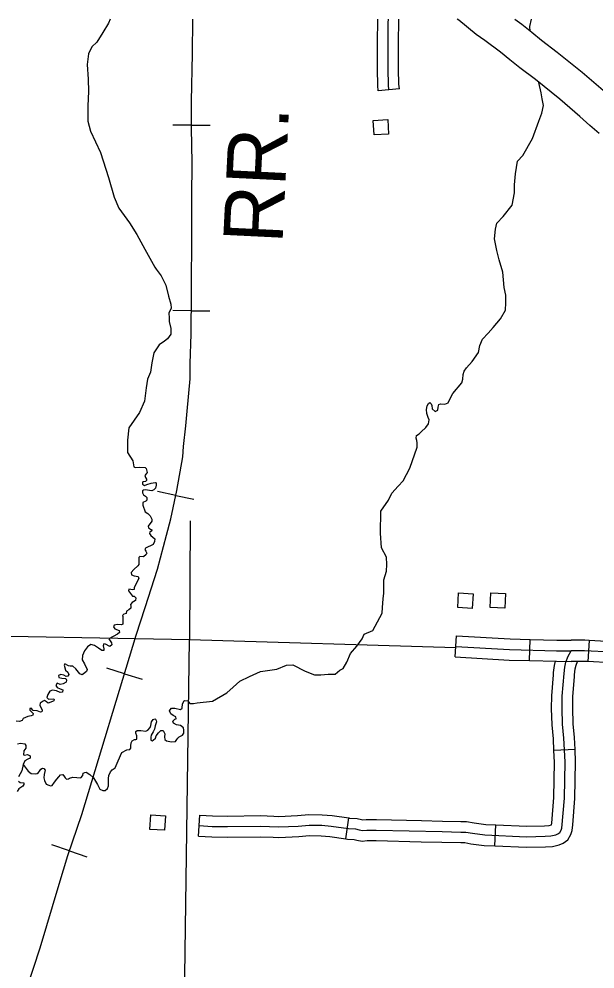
# Model space of a CAD drawing. Extents: x 61396 to 64680, y 55472 to 57605.
# Drawn here: x 62085.6 to 62213.6, y 56474.2 to 56685.3 of the extents above; entities that cross this region are included whole.
import ezdxf

# ---------------------------------------------------------------- set-up
doc = ezdxf.new("R2010")
doc.units = 0
for name, color, linetype in [('15', 7, 'Continuous'), ('32', 7, 'Continuous'), ('35', 7, 'Continuous'), ('40', 7, 'Continuous'), ('45', 7, 'Continuous'), ('5', 7, 'Continuous'), ('56', 7, 'Continuous')]:
    doc.layers.add(name, color=color, linetype=linetype)

msp = doc.modelspace()

# ---------------------------------------------------------------- linework, layer by layer
at = {"layer": '15'}
for points in [[(62214.53, 56659.81), (62212.49, 56661.57), (62210.28, 56663.63), (62205.78, 56667.45), (62200.39, 56671.79), (62196.91, 56674.45), (62194.73, 56676.21), (62192.61, 56677.89), (62189.12, 56680.49), (62187.24, 56681.8), (62183.33, 56685), (62183, 56685.27)], [(62195.78, 56685.27), (62197.37, 56684.09), (62199.61, 56682.31), (62201.74, 56680.59), (62205.21, 56677.93), (62210.76, 56673.47), (62215.48, 56669.46)]]:
    msp.add_lwpolyline(points, dxfattribs=at)
at = {"layer": '32'}
for p, q in [((62170.14, 56669.74), (62165.47, 56669.34)), ((62182.54, 56543.52), (62182.81, 56548.2)), ((62199.09, 56542.71), (62199.22, 56547.39)), ((62212.31, 56547.16), (62212.06, 56542.48))]:
    msp.add_line(p, q, dxfattribs=at)
for points in [[(62165.47, 56669.34), (62165.37, 56670.52), (62165.31, 56674.11), (62165.31, 56680.62), (62165.34, 56684.51), (62165.37, 56685.27)], [(62167.81, 56669.54), (62167.71, 56670.64), (62167.65, 56674.13), (62167.65, 56680.61), (62167.68, 56684.45), (62167.72, 56685.27)], [(62170.14, 56669.74), (62170.05, 56670.76), (62169.99, 56674.15), (62169.99, 56680.6), (62170.02, 56684.39), (62170.06, 56685.27)], [(62182.81, 56548.2), (62194.76, 56547.52), (62199.22, 56547.39)], [(62199.22, 56547.39), (62205.13, 56547.23), (62208.35, 56547.22)], [(62212.31, 56547.16), (62211.36, 56547.22), (62208.35, 56547.22)], [(62228.59, 56546.6), (62227.04, 56546.55), (62220.19, 56546.77), (62217.39, 56546.88), (62212.31, 56547.16)], [(62182.68, 56545.86), (62194.66, 56545.17), (62205.09, 56544.89), (62208.35, 56544.87)], [(62245.16, 56544.7), (62243.79, 56544.59), (62238.85, 56544.62), (62227.04, 56544.2), (62220.1, 56544.43), (62217.28, 56544.54), (62211.29, 56544.87), (62208.35, 56544.87)], [(62182.54, 56543.52), (62194.56, 56542.83), (62199.09, 56542.71)], [(62199.09, 56542.71), (62205.05, 56542.54), (62208.34, 56542.53)], [(62212.06, 56542.48), (62211.23, 56542.53), (62208.34, 56542.53)], [(62228.75, 56541.92), (62227.04, 56541.86), (62220.02, 56542.09), (62217.17, 56542.2), (62212.06, 56542.48)]]:
    msp.add_lwpolyline(points, dxfattribs=at)
at = {"layer": '35'}
for points in [[(62105.84, 56685.27), (62105.46, 56684.33), (62104.2, 56682.24), (62102.87, 56680.13), (62101.79, 56679.08), (62101.05, 56677.56), (62100.73, 56675.17), (62100.95, 56671.91), (62101.04, 56669.15), (62100.88, 56665.98), (62100.91, 56662.59), (62101.53, 56660.31), (62103.73, 56655.59), (62105.5, 56650.05), (62106.73, 56645.67), (62107.76, 56643.27), (62110.14, 56639.94), (62111.79, 56637.38), (62113.57, 56634.1), (62115.83, 56630.11), (62116.09, 56629.7), (62117.17, 56628.21), (62118.22, 56626.09), (62118.81, 56623.68), (62119.32, 56621.92), (62119.43, 56621.02), (62118.93, 56619.88), (62119.01, 56618.88), (62119.01, 56618.06), (62119.37, 56616.46), (62119.35, 56615.24), (62118.64, 56614.23), (62117.96, 56613.69), (62116.72, 56612.89), (62115.54, 56611.09), (62115.09, 56608.89), (62114.83, 56606.81), (62114.19, 56605.2), (62113.83, 56603.29), (62113.52, 56600.33), (62112.38, 56597.84), (62109.98, 56594.42), (62109.7, 56591.7), (62109.74, 56588.94), (62110.87, 56587.11), (62111.12, 56585.73), (62111.44, 56585.57), (62112.33, 56585.69), (62113.63, 56585.63)], [(62199.24, 56682.57), (62199.15, 56683.63), (62199.51, 56685.27)], [(62190.96, 56616.72), (62192.6, 56618.62), (62193.71, 56620.58), (62193.84, 56622.22), (62193.84, 56623.92), (62193.45, 56625.63), (62193.12, 56629.03), (62192.34, 56631.78), (62191.81, 56633.81), (62191.29, 56636.43), (62191.55, 56638.59), (62191.81, 56639.9), (62193.25, 56641.4), (62195.22, 56643.89), (62195.74, 56646.64), (62195.74, 56648.41), (62195.94, 56650.83), (62196.4, 56653.71), (62197.57, 56654.95), (62199.74, 56658.75), (62201.18, 56662.55), (62201.83, 56664.38), (62202.16, 56666.02), (62201.9, 56667.52), (62201.63, 56668.9), (62201.15, 56671.13)], [(62122.19, 56527.72), (62121.48, 56528.25), (62120.6, 56528.43), (62119.95, 56528.78), (62119.83, 56529.25), (62120.25, 56529.66), (62120.54, 56529.78), (62120.48, 56530.19), (62119.89, 56530.49), (62119.36, 56530.9), (62119.07, 56531.54), (62119.19, 56531.78), (62119.48, 56532.13), (62120.25, 56532.13), (62121.48, 56531.84), (62121.89, 56532.13), (62121.95, 56533.07), (62122.3, 56533.72), (62122.48, 56533.84), (62123.13, 56533.72), (62123.6, 56533.19), (62124.36, 56533.19), (62125.19, 56533.31), (62128.6, 56533.66), (62131.77, 56535.54), (62133.18, 56536.83), (62134.71, 56538.13), (62136.83, 56539.19), (62139.3, 56540.24), (62142.94, 56540.83), (62145.06, 56541.66), (62146.47, 56541.77), (62149.18, 56540.36), (62151.3, 56539.54), (62152.71, 56539.54), (62154.35, 56539.66), (62155.88, 56539.66), (62156.94, 56540.6), (62157.65, 56540.95), (62158.47, 56542.36), (62159.29, 56544.24), (62160.7, 56545.89), (62161.88, 56547.54), (62162.35, 56548.59), (62164.23, 56549.42), (62166.34, 56553.22), (62166.41, 56554.53), (62166.54, 56556.43), (62166.67, 56557.67), (62166.73, 56559.05), (62166.67, 56560.68), (62167.32, 56562.58), (62167.39, 56564.02), (62167.26, 56565.66), (62166.21, 56567.75), (62165.95, 56571.03), (62166.01, 56575.87), (62167.72, 56578.36), (62168.5, 56579.93), (62169.88, 56581.44), (62170.99, 56582.61), (62172.5, 56585.49), (62174.07, 56590.14), (62174.07, 56591.12), (62174, 56591.58), (62173.87, 56592.11), (62173.94, 56592.7), (62174.53, 56593.09), (62174.98, 56593.55), (62176.03, 56594.53), (62176.62, 56595.31), (62176.75, 56596.17), (62176.56, 56596.69), (62176.23, 56597.61), (62176.16, 56598.46), (62176.29, 56599.31), (62176.62, 56599.83), (62176.95, 56600.03), (62177.21, 56599.77), (62177.34, 56599.37), (62177.47, 56598.65), (62178.13, 56598.06), (62178.72, 56598.33), (62178.78, 56599.05), (62178.91, 56599.57), (62179.31, 56599.77), (62180.22, 56599.7), (62181.01, 56599.96), (62181.34, 56600.81), (62182.06, 56602.06), (62184.02, 56604.41), (62184.22, 56605.2), (62184.35, 56606.25), (62184.54, 56607.03), (62185.07, 56607.75), (62186.31, 56609.13), (62187.75, 56611.16), (62188.01, 56612.73), (62188.6, 56614.1), (62189.85, 56615.48), (62190.96, 56616.72)], [(62113.63, 56585.63), (62113.9, 56585.42), (62114.07, 56584.5), (62113.86, 56584.21), (62113.57, 56583.82)], [(62113.57, 56583.82), (62113.71, 56583.4), (62113.96, 56583.05), (62113.96, 56582.71), (62113.73, 56582.52), (62113.16, 56582.4), (62113.03, 56582.23), (62113.07, 56581.91), (62113.5, 56581.64), (62114, 56581.81), (62114.99, 56582.14), (62115.84, 56582.31), (62116.09, 56582.19), (62116.09, 56581.68), (62115.94, 56580.98), (62115.58, 56580.65), (62115.1, 56580.44), (62114.63, 56580.52), (62113.75, 56580.67), (62113.24, 56580.6), (62113.05, 56580.39), (62113.03, 56580.01), (62113.24, 56579.55), (62113.71, 56579.25), (62114, 56578.92), (62114.04, 56578.37), (62113.79, 56578.09), (62113.14, 56577.82), (62113.14, 56577.27), (62113.66, 56575.75), (62114.25, 56575.35), (62114.76, 56574.85), (62115.12, 56574.09), (62115.1, 56573.69), (62114.3, 56572.59), (62114.36, 56572.17), (62114.82, 56571.93), (62115.14, 56571.79), (62115.16, 56571.66), (62114.95, 56571.43), (62114.68, 56571.26), (62114.59, 56570.96), (62114.91, 56570.46), (62115.82, 56569.78), (62115.75, 56569.15), (62115.39, 56568.47), (62113.75, 56567.69), (62113.54, 56567.36), (62113.79, 56567), (62114.04, 56566.58), (62113.9, 56566.26), (62113.31, 56565.75), (62112.44, 56565.84), (62112.25, 56565.61), (62112.25, 56564.02), (62112.04, 56563.75), (62111.13, 56562.91), (62110.56, 56562.27), (62110.62, 56561.75), (62111.23, 56561.53), (62112.07, 56561.37), (62112.23, 56560.95), (62111.78, 56560.14), (62111.2, 56558.86), (62111.17, 56558.47), (62110.91, 56558.44), (62110.01, 56558.54), (62109.95, 56558.21), (62110.17, 56557.89), (62110.85, 56557.02), (62111.17, 56557.02), (62111.59, 56556.67), (62111.52, 56556.06), (62110.75, 56555.58), (62110.36, 56555.19), (62110.49, 56554.81), (62110.46, 56554.32), (62110.04, 56554), (62109.53, 56553.68), (62109.4, 56553.2), (62108.89, 56553.01), (62108.6, 56552.75), (62108.69, 56552.49), (62108.69, 56550.79), (62108.4, 56550.66), (62107.47, 56550.72), (62106.73, 56550.59), (62106.57, 56550.18), (62106.92, 56549.73), (62107.89, 56549.37), (62107.92, 56548.95), (62107.5, 56548.6), (62105.57, 56547.54), (62106.18, 56546.63), (62106.24, 56546.17)], [(62106.24, 56546.17), (62105.79, 56545.81), (62104.82, 56546.34), (62104.44, 56546.39), (62104.29, 56546), (62104.49, 56545.33), (62104.49, 56544.94), (62104, 56544.94), (62103.28, 56545.47), (62102.36, 56546.05), (62101.59, 56546.24), (62100.82, 56545.76), (62100.14, 56544.84), (62099.71, 56543.83), (62099.61, 56542.86), (62100.19, 56541.95), (62100.77, 56540.74), (62100.62, 56540.31), (62099.95, 56539.78), (62099.61, 56539.53), (62099.13, 56539.78), (62098.21, 56540.84), (62097.58, 56541.47), (62097, 56541.47), (62096.57, 56541.56), (62095.8, 56542), (62095.65, 56541.71), (62095.94, 56540.6), (62096.42, 56540.11), (62096.67, 56539.58), (62096.47, 56539.24), (62096.09, 56539.15), (62095.56, 56539.49), (62094.88, 56539.58), (62094.35, 56539.39), (62094.45, 56538.95), (62095.12, 56538.76), (62096.04, 56538.71), (62096.13, 56538.38), (62096.09, 56537.94), (62095.41, 56537.51), (62094.78, 56537.36), (62094.11, 56537.65), (62093.82, 56537.17), (62094.06, 56536.69), (62094.78, 56536.44), (62095.31, 56536.2), (62095.27, 56535.67), (62094.73, 56535.62), (62093.96, 56535.96), (62093.05, 56536.11), (62092.42, 56535.91), (62091.98, 56535.14), (62091.79, 56534.47), (62092.13, 56534.13), (62093.33, 56534.22), (62093.43, 56534.08), (62093.33, 56533.79), (62093.05, 56533.6), (62092.08, 56533.26), (62091.74, 56533.5), (62091.26, 56533.84), (62090.97, 56533.65), (62090.29, 56533.21), (62090.24, 56532.78), (62090.73, 56531.67), (62090.68, 56531.28), (62090.39, 56531.23), (62089.67, 56531.52), (62088.75, 56531.62), (62088.31, 56532.15), (62088.02, 56532.05), (62087.98, 56531.67), (62088.36, 56531.28), (62088.75, 56530.94), (62088.7, 56530.6), (62088.31, 56530.41), (62087.59, 56530.27), (62086.53, 56529.83)], [(62086.53, 56529.83), (62086.32, 56529.42), (62085.72, 56529.17), (62084.94, 56529.21)], [(62086.52, 56519.58), (62087.67, 56518.14), (62088.31, 56517.61), (62089.26, 56517.55), (62089.61, 56517.61), (62089.96, 56517.84), (62090.14, 56518.14), (62090.43, 56518.55), (62090.84, 56518.79), (62091.14, 56518.73), (62091.43, 56518.37), (62091.37, 56518.02), (62091.2, 56517.37), (62091.14, 56516.67), (62091.26, 56516.02), (62091.67, 56515.26), (62092.2, 56515.02), (62092.61, 56514.9), (62092.96, 56514.96), (62093.49, 56515.67), (62094.02, 56516.37), (62094.49, 56516.9), (62094.84, 56517.32), (62095.31, 56517.37), (62095.72, 56516.9), (62095.84, 56516.61), (62096.19, 56516.37), (62096.61, 56516.43), (62096.84, 56516.55), (62097.55, 56516.79), (62099.31, 56516.61), (62099.78, 56517.2), (62099.9, 56517.67), (62100.25, 56517.84), (62100.55, 56517.9), (62101.31, 56517.37), (62102.19, 56516.61), (62103.07, 56515.14), (62103.6, 56514.14), (62104.25, 56513.85), (62104.72, 56513.85), (62105.25, 56514.26), (62105.49, 56514.9), (62105.49, 56515.49), (62105.49, 56516.49), (62105.6, 56517.14), (62105.96, 56517.96), (62106.31, 56518.43), (62106.96, 56518.84), (62107.66, 56520.43), (62108.48, 56522.31), (62109.6, 56522.9), (62110.25, 56522.96), (62110.43, 56523.25), (62110.48, 56523.78), (62110.54, 56524.43), (62110.72, 56524.9), (62111.31, 56525.13), (62111.6, 56525.13), (62111.78, 56525.25), (62111.78, 56525.96), (62111.6, 56526.55), (62111.54, 56526.96), (62111.9, 56527.19), (62112.66, 56527.19), (62113.78, 56527.02), (62114.25, 56527.25), (62114.72, 56527.84), (62114.89, 56528.31), (62115.07, 56529.07), (62115.42, 56529.6), (62115.78, 56529.78), (62115.95, 56529.66), (62116.07, 56529.37), (62116.13, 56529.07), (62115.89, 56528.19), (62115.72, 56527.49), (62115.42, 56526.9), (62115.01, 56526.13), (62114.89, 56525.66), (62114.89, 56525.02), (62115.19, 56524.9), (62115.42, 56525.02), (62115.95, 56525.49), (62116.07, 56525.96), (62116.6, 56526.66), (62117.13, 56527.19), (62117.66, 56527.13), (62118.01, 56526.43), (62117.95, 56525.78), (62118.01, 56525.13), (62118.36, 56524.9), (62119.48, 56524.66), (62120.42, 56524.72), (62120.66, 56525.19), (62120.89, 56525.49), (62121.19, 56525.78), (62121.95, 56526.13), (62122.25, 56526.6), (62122.25, 56527.25), (62122.19, 56527.72)], [(62085.29, 56524.19), (62085.93, 56524.33), (62086.89, 56524.19), (62087.14, 56523.84), (62087.14, 56523.27), (62086.68, 56522.66), (62086.57, 56521.75), (62086.8, 56521.66), (62087.5, 56521.84), (62088.1, 56521.52), (62088.1, 56521.05), (62087.54, 56520.82), (62086.89, 56520.41), (62086.52, 56519.58), (62086.25, 56518.19), (62085.51, 56516.89)], [(62085.46, 56515.92), (62085.83, 56515.6), (62086.66, 56515.55), (62086.66, 56515.18), (62086.43, 56514.81), (62085.6, 56514.21), (62085.23, 56513.61)]]:
    msp.add_lwpolyline(points, dxfattribs=at)
at = {"layer": '40'}
for p, q in [((62123.95, 56661.69), (62119.82, 56661.69)), ((62123.95, 56661.69), (62128.07, 56661.69)), ((62123.89, 56620.44), (62119.76, 56620.46)), ((62123.89, 56620.44), (62128.01, 56620.42)), ((62120.44, 56579.41), (62116.4, 56580.25)), ((62120.44, 56579.41), (62124.48, 56578.58)), ((62109.05, 56539.79), (62105.11, 56540.99)), ((62109.05, 56539.79), (62113, 56538.6)), ((62096.79, 56500.41), (62092.89, 56501.75)), ((62096.79, 56500.41), (62100.69, 56499.08))]:
    msp.add_line(p, q, dxfattribs=at)
for points in [[(62087.25, 56469.64), (62090.34, 56478.86), (62094.52, 56493.02), (62096.43, 56499.35), (62099.55, 56508.48), (62111.65, 56548.34), (62113.64, 56554.47), (62116.4, 56562.99), (62118.39, 56570.54), (62119.36, 56574.19), (62120.66, 56580.48), (62122, 56587.99), (62122.2, 56590.31), (62122.69, 56594.85), (62123.01, 56598.1), (62123.62, 56605.32), (62123.62, 56608.69), (62123.87, 56615.22), (62123.91, 56624.52), (62123.99, 56638.12), (62124.03, 56645.7), (62124.07, 56653.29), (62123.95, 56661.05), (62123.95, 56667.01), (62124.15, 56677.52), (62124.22, 56685.27)], [(62119.36, 56574.19), (62120.66, 56580.48), (62122, 56587.99), (62122.2, 56590.31), (62122.69, 56594.85), (62123.01, 56598.1), (62123.62, 56605.32), (62123.62, 56608.69), (62123.87, 56615.22), (62123.91, 56624.52), (62123.99, 56638.12), (62124.03, 56645.7), (62124.07, 56653.29), (62123.95, 56661.05), (62123.95, 56667.01), (62124.15, 56677.52), (62124.22, 56685.27)], [(62087.25, 56469.64), (62090.34, 56478.86), (62094.52, 56493.02), (62096.43, 56499.35), (62099.55, 56508.48), (62111.65, 56548.34), (62113.64, 56554.47), (62116.4, 56562.99), (62118.39, 56570.54), (62119.36, 56574.19)]]:
    msp.add_lwpolyline(points, dxfattribs=at)
at = {"layer": '45'}
for p, q in [((62209.2, 56522.97), (62204.51, 56522.75)), ((62125.52, 56503.68), (62125.79, 56508.36)), ((62158.24, 56503.08), (62158.93, 56507.72)), ((62191.39, 56501.53), (62191.59, 56506.21))]:
    msp.add_line(p, q, dxfattribs=at)
for points in [[(62125.66, 56506.02), (62128.55, 56505.86), (62131.97, 56505.82), (62139.23, 56505.9), (62143.36, 56505.73), (62147.65, 56505.94), (62150.12, 56506.15), (62152.88, 56506.11), (62154.95, 56505.94), (62158.82, 56505.36), (62160.43, 56505.28), (62161.22, 56505.07), (62161.96, 56504.95), (62162.91, 56505.03), (62165.02, 56505.04), (62179.68, 56504.69), (62183.81, 56504.58), (62184.89, 56504.58), (62186.4, 56504.33), (62189.17, 56503.97), (62198.43, 56503.57), (62202.53, 56503.65), (62203.82, 56503.72), (62204.9, 56504.01), (62205.4, 56504.22), (62205.83, 56504.51), (62206.12, 56505.01), (62206.26, 56505.44), (62206.84, 56512.16), (62206.98, 56520.17), (62206.73, 56525.45), (62206.44, 56528.54), (62206.34, 56532.06), (62206.35, 56534.79), (62206.77, 56539.8), (62206.93, 56541.23), (62207.18, 56542.35), (62207.7, 56543.68), (62208.35, 56544.87)], [(62204.39, 56539.52), (62204.43, 56540.03), (62204.61, 56541.63), (62204.82, 56542.55)], [(62209.06, 56539.14), (62209.1, 56539.57), (62209.24, 56540.84), (62209.43, 56541.66), (62209.77, 56542.53)], [(62204.51, 56522.75), (62204.39, 56525.28), (62204.1, 56528.39), (62203.99, 56532.03), (62204.01, 56534.89), (62204.39, 56539.52)], [(62209.2, 56522.97), (62209.07, 56525.61), (62208.78, 56528.68), (62208.68, 56532.09), (62208.7, 56534.68), (62209.06, 56539.14)], [(62204.01, 56506.59), (62204.5, 56512.28), (62204.64, 56520.13), (62204.51, 56522.75)], [(62208.68, 56506.19), (62209.18, 56512.04), (62209.33, 56520.2), (62209.2, 56522.97)], [(62125.79, 56508.36), (62128.63, 56508.2), (62131.97, 56508.16), (62139.26, 56508.24), (62142.24, 56508.12)], [(62142.24, 56508.12), (62143.35, 56508.08), (62147.49, 56508.28), (62150.04, 56508.49), (62153, 56508.45), (62155.21, 56508.27), (62158.93, 56507.72)], [(62158.93, 56507.72), (62159.06, 56507.7), (62160.8, 56507.61), (62161.71, 56507.37), (62162.05, 56507.31), (62162.8, 56507.38), (62165.04, 56507.38), (62175.1, 56507.14)], [(62175.1, 56507.14), (62179.74, 56507.03), (62183.84, 56506.92), (62185.08, 56506.92), (62186.74, 56506.65), (62189.37, 56506.31), (62191.59, 56506.21)], [(62191.39, 56501.53), (62198.4, 56501.23), (62202.61, 56501.3), (62204.19, 56501.39), (62205.67, 56501.78), (62206.52, 56502.15), (62207.59, 56502.87), (62208.27, 56504.05), (62208.58, 56504.97), (62208.68, 56506.19)], [(62191.59, 56506.21), (62198.46, 56505.92), (62202.44, 56505.99), (62203.45, 56506.05), (62203.98, 56506.19), (62204.01, 56506.59)], [(62125.52, 56503.68), (62128.47, 56503.52), (62131.97, 56503.47), (62139.2, 56503.56), (62142.06, 56503.44)], [(62142.06, 56503.44), (62143.36, 56503.39), (62147.8, 56503.6), (62150.2, 56503.8), (62152.77, 56503.76), (62154.68, 56503.61), (62158.24, 56503.08)], [(62158.24, 56503.08), (62158.59, 56503.03), (62160.07, 56502.95), (62160.72, 56502.78), (62161.87, 56502.59), (62163.01, 56502.69), (62164.99, 56502.7), (62174.98, 56502.46)], [(62174.98, 56502.46), (62179.62, 56502.35), (62183.78, 56502.24), (62184.7, 56502.24), (62186.06, 56502.01), (62188.96, 56501.63), (62191.39, 56501.53)]]:
    msp.add_lwpolyline(points, dxfattribs=at)
at = {"layer": '5'}
for points in [[(62123.67, 56573.72), (62123.47, 56547.31)], [(62123.47, 56547.31), (62011.81, 56549.4)], [(62121.21, 56382.06), (62123.47, 56547.31)], [(62182.66, 56545.51), (62123.47, 56547.31)]]:
    msp.add_lwpolyline(points, dxfattribs=at)
at = {"layer": '56'}
for points in [[(62164.51, 56659.5), (62164.35, 56662.75), (62167.61, 56662.91), (62167.76, 56659.66)], [(62183.11, 56554.51), (62183.31, 56557.76), (62186.57, 56557.55), (62186.36, 56554.31)], [(62190.34, 56554.51), (62190.48, 56557.76), (62193.74, 56557.62), (62193.6, 56554.37)], [(62114.67, 56505.19), (62114.88, 56508.44), (62118.14, 56508.23), (62117.93, 56504.99)]]:
    msp.add_lwpolyline(points, close=True, dxfattribs=at)

# ---------------------------------------------------------------- texts
at = {"layer": '40'}
msp.add_text('RR.', height=13.2, rotation=87.2069, dxfattribs=at).set_placement((62144.15, 56635.22))

doc.saveas('drawing.dxf')
